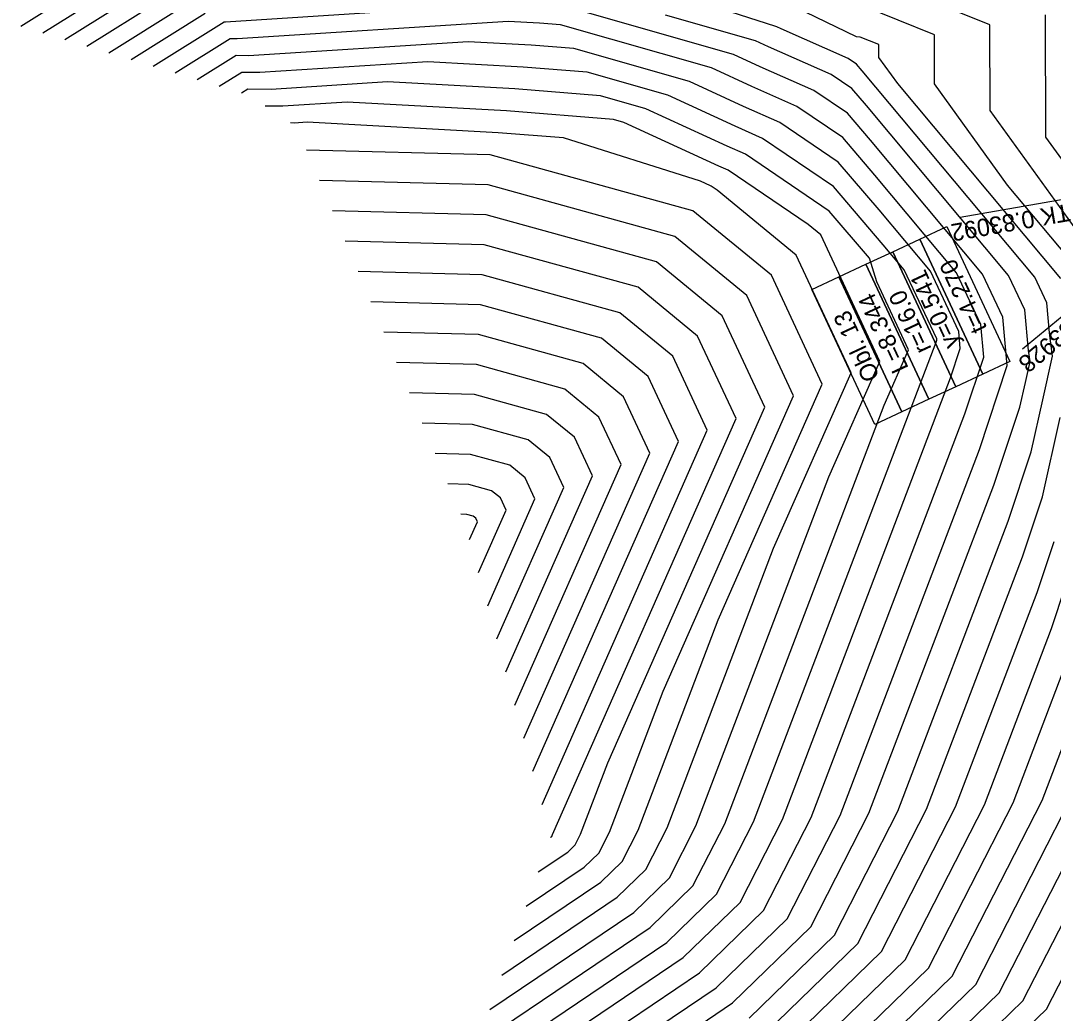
# Model space of a CAD drawing. Extents: x -549394 to -546608, y -1037055 to -1033629.
# Drawn here: x -547404 to -547196, y -1036462.8 to -1036262.8 of the extents above; entities that cross this region are included whole.
import ezdxf

# ---------------------------------------------------------------- set-up
doc = ezdxf.new("R2010")
doc.units = 0
for name, color, linetype in [('hlavni_vrst', 7, 'Continuous'), ('norm_vrst', 7, 'Continuous'), ('x_popis_oblouky_C31', 7, 'Continuous')]:
    doc.layers.add(name, color=color, linetype=linetype)

msp = doc.modelspace()

# ---------------------------------------------------------------- linework, layer by layer
at = {"layer": 'hlavni_vrst'}
for p, q in [((-547390.42, -1036255.49), (-547404.04, -1036264)), ((-547366.84, -1036261.38), (-547381.81, -1036270.72)), ((-547256.01, -1036266.88), (-547274.12, -1036261.72)), ((-547197.5, -1036286.3), (-547197.57, -1036261.66)), ((-547253.37, -1036268.09), (-547256.01, -1036266.88)), ((-547240.76, -1036273.66), (-547253.37, -1036268.09)), ((-547236.58, -1036276.5), (-547240.76, -1036273.66)), ((-547330.13, -1036275.17), (-547353.55, -1036276.68)), ((-547304.5, -1036276.58), (-547330.13, -1036275.17)), ((-547358.25, -1036276.62), (-547359.58, -1036277.45)), ((-547353.55, -1036276.68), (-547358.25, -1036276.62)), ((-547287.25, -1036277.96), (-547304.5, -1036276.58)), ((-547278.11, -1036280.57), (-547287.25, -1036277.96)), ((-547233.65, -1036279.92), (-547236.58, -1036276.5)), ((-547205, -1036314.18), (-547233.65, -1036279.92)), ((-547261.73, -1036288.11), (-547278.11, -1036280.57)), ((-547180.18, -1036310.3), (-547197.5, -1036286.3)), ((-547258.02, -1036289.75), (-547261.73, -1036288.11)), ((-547241.17, -1036301.18), (-547258.02, -1036289.75)), ((-547310.24, -1036301.95), (-547341.25, -1036301.11)), ((-547275.97, -1036311.4), (-547310.24, -1036301.95)), ((-547233.04, -1036310.68), (-547241.17, -1036301.18)), ((-547262.71, -1036322.27), (-547275.97, -1036311.4)), ((-547231.58, -1036315.41), (-547233.04, -1036310.68)), ((-547225.17, -1036329.14), (-547231.58, -1036315.41)), ((-547201.75, -1036321.09), (-547205, -1036314.18)), ((-547200.98, -1036329.25), (-547201.75, -1036321.09)), ((-547254.12, -1036340.68), (-547262.71, -1036322.27)), ((-547230.08, -1036340.27), (-547225.17, -1036329.14)), ((-547200.69, -1036331.48), (-547200.98, -1036329.25)), ((-547312.21, -1036332.11), (-547328.31, -1036331.67)), ((-547294.41, -1036337.02), (-547312.21, -1036332.11)), ((-547201.63, -1036335.68), (-547200.69, -1036331.48)), ((-547202.75, -1036340.66), (-547201.63, -1036335.68)), ((-547287.53, -1036342.66), (-547294.41, -1036337.02)), ((-547262.19, -1036424.59), (-547230.08, -1036340.27)), ((-547283.06, -1036352.22), (-547287.53, -1036342.66)), ((-547285.76, -1036412.31), (-547254.12, -1036340.68)), ((-547207.98, -1036356.41), (-547202.75, -1036340.66)), ((-547304.48, -1036400.68), (-547283.06, -1036352.22)), ((-547233.13, -1036422.47), (-547207.98, -1036356.41)), ((-547314.17, -1036362.27), (-547315.37, -1036362.23)), ((-547312.85, -1036362.63), (-547314.17, -1036362.27)), ((-547312.34, -1036363.05), (-547312.85, -1036362.63)), ((-547312.01, -1036363.76), (-547312.34, -1036363.05)), ((-547313.6, -1036367.35), (-547312.01, -1036363.76)), ((-547204.08, -1036420.35), (-547193.45, -1036392.43)), ((-547291.24, -1036426.71), (-547285.76, -1036412.31)), ((-547221.12, -1036453.65), (-547204.08, -1036420.35)), ((-547244.86, -1036445.38), (-547233.13, -1036422.47)), ((-547268.6, -1036437.12), (-547262.19, -1036424.59)), ((-547292.34, -1036428.85), (-547291.24, -1036426.71)), ((-547293.81, -1036430.28), (-547292.34, -1036428.85)), ((-547299.75, -1036434.28), (-547293.81, -1036430.28)), ((-547277.21, -1036445.47), (-547268.6, -1036437.12)), ((-547197.38, -1036461.91), (-547187.53, -1036442.68)), ((-547311.97, -1036468.9), (-547277.21, -1036445.47)), ((-547260.62, -1036460.67), (-547244.86, -1036445.38)), ((-547244.02, -1036475.86), (-547221.12, -1036453.65)), ((-547324.2, -1036503.52), (-547260.62, -1036460.67)), ((-547227.42, -1036491.06), (-547197.38, -1036461.91))]:
    msp.add_line(p, q, dxfattribs=at)
at = {"layer": 'norm_vrst'}
for p, q in [((-547251.9, -1036264.01), (-547294.29, -1036250.29)), ((-547208.76, -1036263.66), (-547234.26, -1036253.4)), ((-547385.7, -1036256.67), (-547399.6, -1036265.34)), ((-547380.99, -1036257.85), (-547395.15, -1036266.69)), ((-547376.27, -1036259.02), (-547390.71, -1036268.03)), ((-547302.54, -1036259.26), (-547362.75, -1036263.13)), ((-547260.43, -1036269.62), (-547297.39, -1036259.08)), ((-547235.62, -1036266.08), (-547249.97, -1036259.18)), ((-547371.55, -1036260.2), (-547386.26, -1036269.38)), ((-547219.95, -1036265.66), (-547234.6, -1036259.76)), ((-547363.04, -1036263.13), (-547377.37, -1036272.07)), ((-547362.75, -1036263.13), (-547363.04, -1036263.13)), ((-547305.81, -1036263.01), (-547360.45, -1036266.52)), ((-547299.5, -1036263.35), (-547305.81, -1036263.01)), ((-547295.25, -1036263.69), (-547299.5, -1036263.35)), ((-547264.85, -1036272.35), (-547295.25, -1036263.69)), ((-547251.7, -1036264.05), (-547251.9, -1036264.01)), ((-547250.8, -1036264.49), (-547251.7, -1036264.05)), ((-547237.3, -1036270.44), (-547250.8, -1036264.49)), ((-547219.92, -1036275.58), (-547219.95, -1036265.66)), ((-547208.71, -1036280.94), (-547208.76, -1036263.66)), ((-547361.84, -1036266.5), (-547372.92, -1036273.41)), ((-547360.45, -1036266.52), (-547361.84, -1036266.5)), ((-547313.91, -1036267.06), (-547358.15, -1036269.9)), ((-547301.16, -1036267.76), (-547313.91, -1036267.06)), ((-547234.94, -1036266.12), (-547235.62, -1036266.08)), ((-547231.14, -1036267.65), (-547234.94, -1036266.12)), ((-547231.14, -1036270.23), (-547231.14, -1036267.65)), ((-547292.58, -1036268.45), (-547301.16, -1036267.76)), ((-547269.27, -1036275.09), (-547292.58, -1036268.45)), ((-547255.04, -1036272.1), (-547260.43, -1036269.62)), ((-547360.64, -1036269.87), (-547368.48, -1036274.76)), ((-547358.15, -1036269.9), (-547360.64, -1036269.87)), ((-547322.02, -1036271.12), (-547355.85, -1036273.29)), ((-547302.83, -1036272.17), (-547322.02, -1036271.12)), ((-547235.66, -1036271.56), (-547237.3, -1036270.44)), ((-547234.51, -1036272.91), (-547235.66, -1036271.56)), ((-547227.33, -1036275.5), (-547231.14, -1036270.23)), ((-547359.45, -1036273.24), (-547364.03, -1036276.1)), ((-547355.85, -1036273.29), (-547359.45, -1036273.24)), ((-547289.92, -1036273.21), (-547302.83, -1036272.17)), ((-547273.69, -1036277.83), (-547289.92, -1036273.21)), ((-547256.71, -1036276.1), (-547264.85, -1036272.35)), ((-547244.21, -1036276.88), (-547255.04, -1036272.1)), ((-547199.74, -1036314.48), (-547234.51, -1036272.91)), ((-547258.38, -1036280.1), (-547269.27, -1036275.09)), ((-547194.49, -1036314.77), (-547227.33, -1036275.5)), ((-547205.23, -1036295.94), (-547219.92, -1036275.58)), ((-547260.06, -1036284.11), (-547273.69, -1036277.83)), ((-547247.66, -1036280.09), (-547256.71, -1036276.1)), ((-547237.49, -1036281.43), (-547244.21, -1036276.88)), ((-547351.25, -1036280.07), (-547354.75, -1036280.02)), ((-547338.24, -1036279.23), (-547351.25, -1036280.07)), ((-547306.17, -1036281), (-547338.24, -1036279.23)), ((-547251.11, -1036283.31), (-547258.38, -1036280.1)), ((-547238.41, -1036286.37), (-547247.66, -1036280.09)), ((-547284.58, -1036282.72), (-547306.17, -1036281)), ((-547232.8, -1036286.93), (-547237.49, -1036281.43)), ((-547184.05, -1036315.11), (-547208.71, -1036280.94)), ((-547348.95, -1036283.45), (-547349.65, -1036283.44)), ((-547346.34, -1036283.29), (-547348.95, -1036283.45)), ((-547307.84, -1036285.41), (-547346.34, -1036283.29)), ((-547282.53, -1036283.31), (-547284.58, -1036282.72)), ((-547263.4, -1036292.12), (-547282.53, -1036283.31)), ((-547254.57, -1036286.53), (-547260.06, -1036284.11)), ((-547239.33, -1036291.31), (-547251.11, -1036283.31)), ((-547294.71, -1036286.46), (-547307.84, -1036285.41)), ((-547267.08, -1036295.19), (-547294.71, -1036286.46)), ((-547231.95, -1036293.93), (-547238.41, -1036286.37)), ((-547240.25, -1036296.24), (-547254.57, -1036286.53)), ((-547210.26, -1036313.88), (-547232.8, -1036286.93)), ((-547309.46, -1036289.88), (-547346.43, -1036288.88)), ((-547268.59, -1036301.15), (-547309.46, -1036289.88)), ((-547261.47, -1036292.96), (-547263.4, -1036292.12)), ((-547231.09, -1036300.94), (-547239.33, -1036291.31)), ((-547245.39, -1036303.87), (-547261.47, -1036292.96)), ((-547215.51, -1036313.59), (-547231.95, -1036293.93)), ((-547309.85, -1036295.91), (-547343.84, -1036295)), ((-547272.28, -1036306.28), (-547309.85, -1036295.91)), ((-547265.07, -1036296.12), (-547267.08, -1036295.19)), ((-547264.92, -1036296.18), (-547265.07, -1036296.12)), ((-547263.73, -1036296.99), (-547264.92, -1036296.18)), ((-547230.24, -1036307.95), (-547240.25, -1036296.24)), ((-547189.23, -1036315.07), (-547205.23, -1036295.94)), ((-547247.82, -1036310.03), (-547263.73, -1036296.99)), ((-547220.77, -1036313.29), (-547231.09, -1036300.94)), ((-547252.78, -1036314.11), (-547268.59, -1036301.15)), ((-547242.85, -1036305.95), (-547245.39, -1036303.87)), ((-547310.63, -1036307.98), (-547338.66, -1036307.22)), ((-547257.74, -1036318.19), (-547272.28, -1036306.28)), ((-547230.96, -1036331.45), (-547242.85, -1036305.95)), ((-547279.66, -1036316.52), (-547310.63, -1036307.98)), ((-547226.02, -1036312.99), (-547230.24, -1036307.95)), ((-547236.75, -1036333.76), (-547247.82, -1036310.03)), ((-547311.03, -1036314.01), (-547336.07, -1036313.33)), ((-547219.49, -1036326.9), (-547226.02, -1036312.99)), ((-547215.05, -1036325.45), (-547220.77, -1036313.29)), ((-547283.35, -1036321.65), (-547311.03, -1036314.01)), ((-547242.54, -1036336.07), (-547252.78, -1036314.11)), ((-547210.62, -1036324), (-547215.51, -1036313.59)), ((-547206.19, -1036322.54), (-547210.26, -1036313.88)), ((-547197.32, -1036319.64), (-547199.74, -1036314.48)), ((-547267.67, -1036326.35), (-547279.66, -1036316.52)), ((-547311.42, -1036320.04), (-547333.49, -1036319.45)), ((-547248.33, -1036338.37), (-547257.74, -1036318.19)), ((-547196.74, -1036325.73), (-547197.32, -1036319.64)), ((-547287.04, -1036326.77), (-547311.42, -1036320.04)), ((-547272.64, -1036330.42), (-547283.35, -1036321.65)), ((-547205.27, -1036332.3), (-547206.19, -1036322.54)), ((-547311.81, -1036326.07), (-547330.9, -1036325.56)), ((-547214.73, -1036328.87), (-547215.05, -1036325.45)), ((-547210, -1036330.58), (-547210.62, -1036324)), ((-547196.14, -1036330.4), (-547196.74, -1036325.73)), ((-547290.72, -1036331.89), (-547311.81, -1036326.07)), ((-547277.6, -1036334.5), (-547287.04, -1036326.77)), ((-547259.91, -1036342.99), (-547267.67, -1036326.35)), ((-547256.38, -1036424.17), (-547219.61, -1036327.6)), ((-547219.61, -1036327.6), (-547219.46, -1036327.16)), ((-547219.46, -1036327.16), (-547219.49, -1036326.9)), ((-547216.7, -1036334.8), (-547214.73, -1036328.87)), ((-547282.56, -1036338.58), (-547290.72, -1036331.89)), ((-547265.7, -1036345.3), (-547272.64, -1036330.42)), ((-547241.22, -1036354.68), (-547230.96, -1036331.45)), ((-547213.79, -1036342), (-547210, -1036330.58)), ((-547198.11, -1036339.23), (-547196.14, -1036330.4)), ((-547252.35, -1036369.09), (-547236.75, -1036333.76)), ((-547210.89, -1036349.21), (-547205.27, -1036332.3)), ((-547271.49, -1036347.6), (-547277.6, -1036334.5)), ((-547263.49, -1036383.5), (-547242.54, -1036336.07)), ((-547250.57, -1036423.74), (-547216.7, -1036334.8)), ((-547312.6, -1036338.14), (-547325.72, -1036337.78)), ((-547298.1, -1036342.14), (-547312.6, -1036338.14)), ((-547274.63, -1036397.9), (-547248.33, -1036338.37)), ((-547277.28, -1036349.91), (-547282.56, -1036338.58)), ((-547200.44, -1036349.68), (-547198.11, -1036339.23)), ((-547292.49, -1036346.74), (-547298.1, -1036342.14)), ((-547244.76, -1036423.32), (-547213.79, -1036342)), ((-547312.99, -1036344.17), (-547323.13, -1036343.9)), ((-547301.79, -1036347.26), (-547312.99, -1036344.17)), ((-547296.9, -1036426.72), (-547259.91, -1036342.99)), ((-547198.14, -1036358.71), (-547194.58, -1036342.79)), ((-547299, -1036420.68), (-547265.7, -1036345.3)), ((-547288.85, -1036354.53), (-547292.49, -1036346.74)), ((-547297.45, -1036350.81), (-547301.79, -1036347.26)), ((-547300.83, -1036414.02), (-547271.49, -1036347.6)), ((-547313.39, -1036350.2), (-547320.54, -1036350.01)), ((-547305.48, -1036352.38), (-547313.39, -1036350.2)), ((-547302.65, -1036407.35), (-547277.28, -1036349.91)), ((-547294.64, -1036356.83), (-547297.45, -1036350.81)), ((-547238.94, -1036422.9), (-547210.89, -1036349.21)), ((-547205.07, -1036363.62), (-547200.44, -1036349.68)), ((-547302.42, -1036354.89), (-547305.48, -1036352.38)), ((-547306.3, -1036394.01), (-547288.85, -1036354.53)), ((-547300.43, -1036359.14), (-547302.42, -1036354.89)), ((-547268, -1036425.02), (-547241.22, -1036354.68)), ((-547313.78, -1036356.23), (-547317.95, -1036356.12)), ((-547309.17, -1036357.51), (-547313.78, -1036356.23)), ((-547308.13, -1036387.35), (-547294.64, -1036356.83)), ((-547309.95, -1036380.68), (-547300.43, -1036359.14)), ((-547307.38, -1036358.97), (-547309.17, -1036357.51)), ((-547306.22, -1036361.45), (-547307.38, -1036358.97)), ((-547202.17, -1036370.82), (-547198.14, -1036358.71)), ((-547311.78, -1036374.01), (-547306.22, -1036361.45)), ((-547227.32, -1036422.05), (-547205.07, -1036363.62)), ((-547273.81, -1036425.44), (-547252.35, -1036369.09)), ((-547199.26, -1036378.02), (-547195.84, -1036367.73)), ((-547221.51, -1036421.62), (-547202.17, -1036370.82)), ((-547215.7, -1036421.2), (-547199.26, -1036378.02)), ((-547196.35, -1036385.23), (-547193.54, -1036376.75)), ((-547279.62, -1036425.87), (-547263.49, -1036383.5)), ((-547209.89, -1036420.78), (-547196.35, -1036385.23)), ((-547285.43, -1036426.29), (-547274.63, -1036397.9)), ((-547198.27, -1036419.93), (-547190.54, -1036399.64)), ((-547211.62, -1036456.95), (-547192.46, -1036419.5)), ((-547206.88, -1036458.61), (-547186.65, -1036419.08)), ((-547235.36, -1036448.69), (-547221.51, -1036421.62)), ((-547230.62, -1036450.34), (-547215.7, -1036421.2)), ((-547225.87, -1036451.99), (-547209.89, -1036420.78)), ((-547216.37, -1036455.3), (-547198.27, -1036419.93)), ((-547259.1, -1036440.42), (-547250.57, -1036423.74)), ((-547254.36, -1036442.08), (-547244.76, -1036423.32)), ((-547249.61, -1036443.73), (-547238.94, -1036422.9)), ((-547240.11, -1036447.04), (-547227.32, -1036422.05)), ((-547282.84, -1036432.16), (-547279.62, -1036425.87)), ((-547278.1, -1036433.81), (-547273.81, -1036425.44)), ((-547273.35, -1036435.46), (-547268, -1036425.02)), ((-547263.85, -1036438.77), (-547256.38, -1036424.17)), ((-547202.13, -1036460.26), (-547184.01, -1036424.86)), ((-547297.3, -1036427.36), (-547297.13, -1036427.24)), ((-547297.13, -1036427.24), (-547297.09, -1036427.2)), ((-547297.09, -1036427.2), (-547297.06, -1036427.14)), ((-547297.06, -1036427.14), (-547296.9, -1036426.72)), ((-547287.59, -1036430.51), (-547285.43, -1036426.29)), ((-547290.49, -1036433.32), (-547287.59, -1036430.51)), ((-547302.19, -1036441.2), (-547290.49, -1036433.32)), ((-547287.17, -1036436.36), (-547282.84, -1036432.16)), ((-547283.85, -1036439.4), (-547278.1, -1036433.81)), ((-547280.53, -1036442.44), (-547273.35, -1036435.46)), ((-547304.64, -1036448.13), (-547287.17, -1036436.36)), ((-547307.08, -1036455.05), (-547283.85, -1036439.4)), ((-547273.89, -1036448.51), (-547263.85, -1036438.77)), ((-547270.57, -1036451.55), (-547259.1, -1036440.42)), ((-547309.53, -1036461.98), (-547280.53, -1036442.44)), ((-547267.25, -1036454.59), (-547254.36, -1036442.08)), ((-547263.93, -1036457.63), (-547249.61, -1036443.73)), ((-547314.42, -1036475.82), (-547273.89, -1036448.51)), ((-547257.3, -1036463.71), (-547240.11, -1036447.04)), ((-547253.98, -1036466.75), (-547235.36, -1036448.69)), ((-547250.66, -1036469.78), (-547230.62, -1036450.34)), ((-547316.86, -1036482.75), (-547270.57, -1036451.55)), ((-547247.34, -1036472.82), (-547225.87, -1036451.99)), ((-547319.31, -1036489.67), (-547267.25, -1036454.59)), ((-547240.7, -1036478.9), (-547216.37, -1036455.3)), ((-547237.38, -1036481.94), (-547211.62, -1036456.95)), ((-547321.76, -1036496.59), (-547263.93, -1036457.63)), ((-547234.06, -1036484.98), (-547206.88, -1036458.61)), ((-547230.74, -1036488.02), (-547202.13, -1036460.26))]:
    msp.add_line(p, q, dxfattribs=at)
at = {"layer": 'x_popis_oblouky_C31'}
for points in [[(-547173.98, -1036295.34), (-547214.74, -1036302.48)], [(-547170.25, -1036302.7), (-547202.17, -1036329.02)]]:
    msp.add_lwpolyline(points, dxfattribs=at)
for points in [[(-547210.22, -1036334.02), (-547222.89, -1036306.83), (-547217.46, -1036304.29), (-547204.78, -1036331.48)], [(-547215.66, -1036336.55), (-547228.33, -1036309.36), (-547222.89, -1036306.83), (-547210.22, -1036334.02)], [(-547221.1, -1036339.09), (-547233.77, -1036311.9), (-547228.33, -1036309.36), (-547215.66, -1036336.55)], [(-547226.54, -1036341.62), (-547239.21, -1036314.43), (-547233.77, -1036311.9), (-547221.1, -1036339.09)], [(-547231.97, -1036344.16), (-547244.65, -1036316.97), (-547239.21, -1036314.43), (-547226.54, -1036341.62)]]:
    msp.add_lwpolyline(points, close=True, dxfattribs=at)

# ---------------------------------------------------------------- texts
for s, rotation, p in [('TK 0.83092', 189.9439, (-547192.97, -1036299.68)), ('t=4.270', 115.0122, (-547209.24, -1036324.78)), ('y=0.541', 115.0122, (-547214.8, -1036327.89)), ('r=16.0', 115.0122, (-547220.47, -1036328.87)), ('KT 0.83928', 219.4972, (-547184.66, -1036315.87)), ('L=8.344', 115.0122, (-547225.07, -1036332.81)), ('Obl. 13', 115.0122, (-547230.88, -1036334.55))]:
    msp.add_text(s, height=3.5, rotation=rotation, dxfattribs=at).set_placement(p)

doc.saveas('drawing.dxf')
